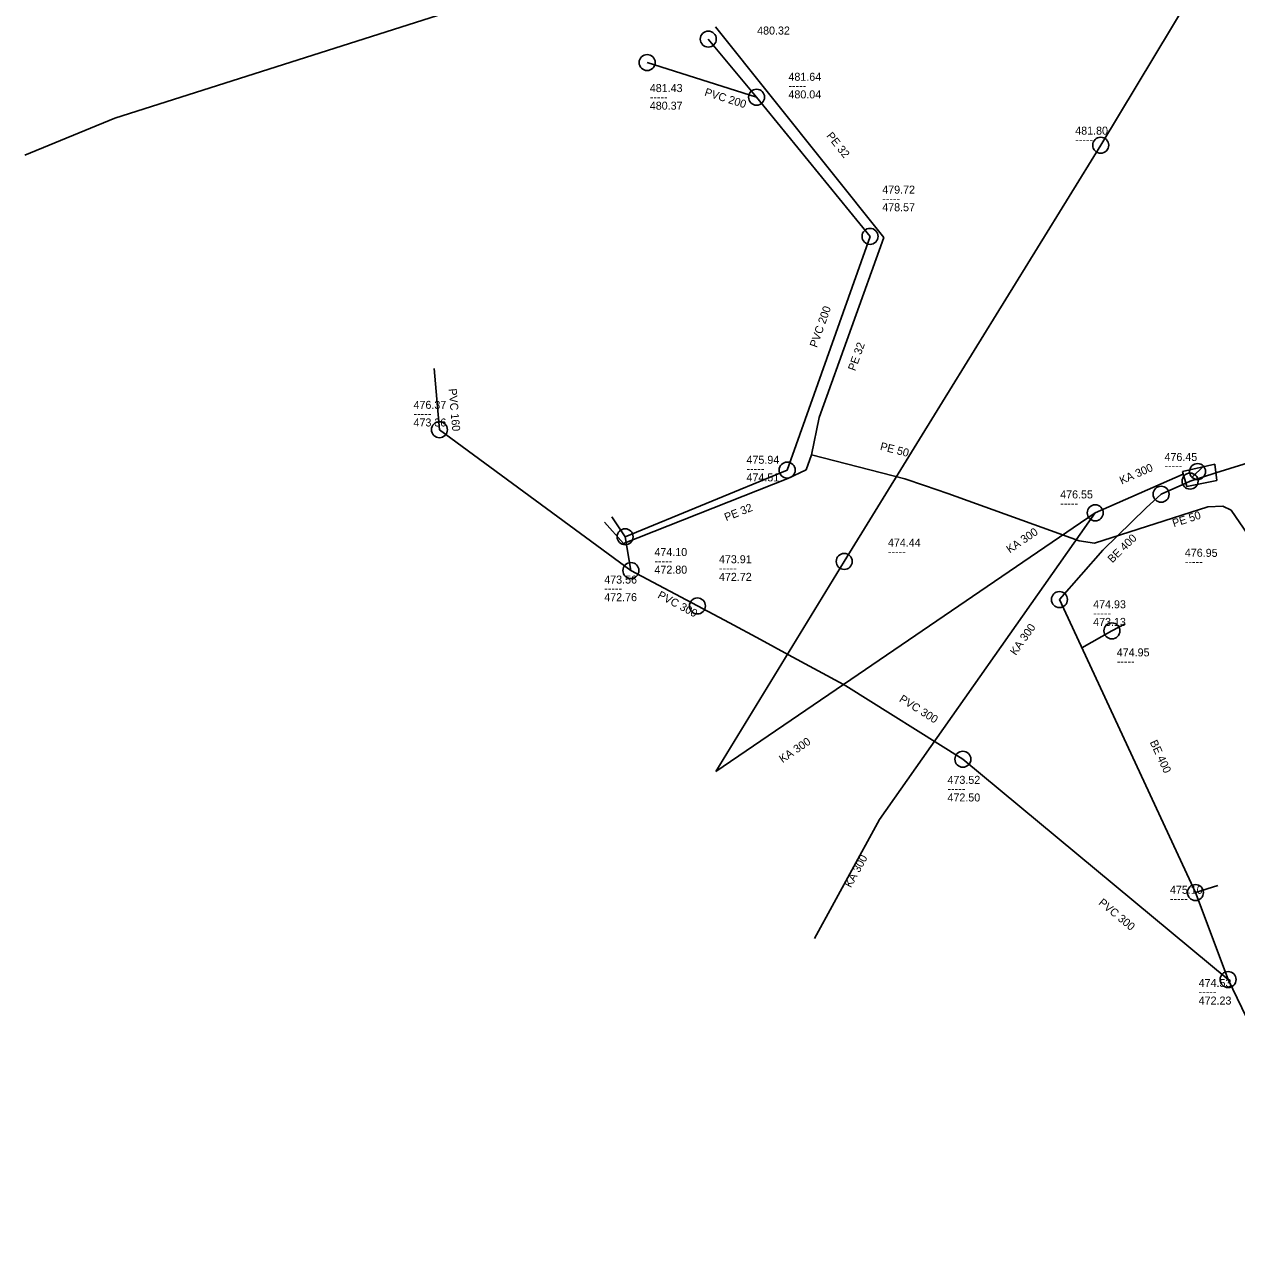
# Model space of a CAD drawing. Extents: x -685576 to -685145, y -1163436 to -1162895.
# Drawn here: x -685575.9 to -685424.5, y -1163249.3 to -1163094.7 of the extents above; entities that cross this region are included whole.
import ezdxf

# ---------------------------------------------------------------- set-up
doc = ezdxf.new("R2010")
doc.units = 0
doc.layers.add('Level 0', color=7, linetype='Continuous')

msp = doc.modelspace()

# ---------------------------------------------------------------- linework, layer by layer
at = {"layer": 'Level 0'}
for p, q in [((-685415.3, -1163066.26), (-685441.48, -1163109.74)), ((-685564.65, -1163106.35), (-685507.45, -1163088.13)), ((-685468.58, -1163121.27), (-685489.59, -1163094.93)), ((-685490.5, -1163096.48), (-685484.47, -1163103.74)), ((-685498.14, -1163099.41), (-685484.47, -1163103.74)), ((-685484.47, -1163103.74), (-685470.3, -1163121.13)), ((-685575.9, -1163110.98), (-685564.65, -1163106.35)), ((-685441.48, -1163109.74), (-685461.23, -1163141.8)), ((-685470.3, -1163121.13), (-685480.65, -1163150.34)), ((-685476.64, -1163143.78), (-685468.58, -1163121.27)), ((-685524.77, -1163137.65), (-685524.09, -1163145.29)), ((-685461.23, -1163141.8), (-685473.52, -1163161.75)), ((-685477.6, -1163148.45), (-685476.64, -1163143.78)), ((-685524.09, -1163145.29), (-685500.17, -1163162.89)), ((-685478.29, -1163150.31), (-685477.6, -1163148.45)), ((-685465.95, -1163151.42), (-685477.6, -1163148.45)), ((-685431.26, -1163150.5), (-685427.24, -1163149.59)), ((-685430.06, -1163151.24), (-685428.65, -1163149.84)), ((-685427.24, -1163149.59), (-685426.99, -1163151.64)), ((-685421.86, -1163149.04), (-685427.1, -1163150.7)), ((-685501.08, -1163159.52), (-685480.57, -1163151.37)), ((-685480.65, -1163150.34), (-685500.89, -1163158.67)), ((-685480.57, -1163151.37), (-685478.29, -1163150.31)), ((-685463.51, -1163152.26), (-685465.95, -1163151.42)), ((-685431.17, -1163150.84), (-685442.16, -1163155.68)), ((-685430.73, -1163152.41), (-685431.26, -1163150.5)), ((-685427.1, -1163150.7), (-685430.31, -1163151.72)), ((-685460.57, -1163153.27), (-685463.51, -1163152.26)), ((-685430.85, -1163151.97), (-685433.93, -1163153.36)), ((-685430.31, -1163151.72), (-685430.85, -1163151.97)), ((-685426.99, -1163151.64), (-685430.73, -1163152.41)), ((-685444.15, -1163159.2), (-685460.57, -1163153.27)), ((-685433.93, -1163153.36), (-685435.79, -1163155.04)), ((-685442.16, -1163155.68), (-685473.63, -1163177.15)), ((-685442.16, -1163155.68), (-685469.11, -1163194.02)), ((-685428.11, -1163154.92), (-685442.27, -1163159.47)), ((-685435.79, -1163155.04), (-685441.2, -1163160.33)), ((-685426.2, -1163154.83), (-685428.11, -1163154.92)), ((-685425.17, -1163155.33), (-685426.2, -1163154.83)), ((-685420.25, -1163162.58), (-685425.17, -1163155.33)), ((-685503.45, -1163156.85), (-685501.08, -1163159.52)), ((-685502.54, -1163156.16), (-685500.89, -1163158.67)), ((-685500.89, -1163158.67), (-685500.17, -1163162.89)), ((-685441.2, -1163160.33), (-685446.64, -1163166.52)), ((-685442.27, -1163159.47), (-685444.15, -1163159.2)), ((-685473.52, -1163161.75), (-685489.56, -1163188.02)), ((-685500.17, -1163162.89), (-685491.86, -1163167.32)), ((-685446.64, -1163166.52), (-685429.64, -1163203.13)), ((-685491.86, -1163167.32), (-685487.84, -1163169.43)), ((-685487.84, -1163169.43), (-685483.99, -1163171.52)), ((-685438.42, -1163169.57), (-685440.08, -1163170.43)), ((-685483.99, -1163171.52), (-685480.5, -1163173.42)), ((-685440.08, -1163170.43), (-685443.82, -1163172.57)), ((-685480.5, -1163173.42), (-685473.62, -1163177.13)), ((-685473.63, -1163177.15), (-685489.56, -1163188.02)), ((-685473.62, -1163177.13), (-685473.33, -1163177.29)), ((-685473.33, -1163177.29), (-685458.7, -1163186.47)), ((-685458.7, -1163186.47), (-685425.56, -1163214)), ((-685469.11, -1163194.02), (-685469.86, -1163195.39)), ((-685469.86, -1163195.39), (-685477.25, -1163208.86)), ((-685426.85, -1163202.27), (-685429.64, -1163203.13)), ((-685429.64, -1163203.13), (-685425.56, -1163214)), ((-685425.56, -1163214), (-685408.59, -1163249.33))]:
    msp.add_line(p, q, dxfattribs=at)
for centre in [(-685490.5, -1163096.48), (-685498.14, -1163099.41), (-685484.47, -1163103.74), (-685441.48, -1163109.74), (-685470.3, -1163121.13), (-685524.09, -1163145.29), (-685480.65, -1163150.34), (-685429.37, -1163150.52), (-685430.31, -1163151.72), (-685433.93, -1163153.36), (-685442.16, -1163155.68), (-685500.89, -1163158.67), (-685500.17, -1163162.89), (-685473.52, -1163161.75), (-685491.86, -1163167.32), (-685446.64, -1163166.52), (-685440.08, -1163170.43), (-685458.7, -1163186.47), (-685429.64, -1163203.13), (-685425.56, -1163214)]:
    msp.add_circle(centre, 1, dxfattribs=at)

# ---------------------------------------------------------------- texts
for s, p in [('480.32', (-685484.4, -1163095.91)), ('481.64', (-685480.49, -1163101.69)), ('481.43', (-685497.81, -1163103.1)), ('480.04', (-685480.49, -1163103.89)), ('-----', (-685480.49, -1163102.79)), ('480.37', (-685497.81, -1163105.3)), ('-----', (-685497.81, -1163104.2)), ('481.80', (-685444.66, -1163108.42)), ('-----', (-685444.66, -1163109.52)), ('479.72', (-685468.77, -1163115.79)), ('478.57', (-685468.77, -1163117.99)), ('-----', (-685468.77, -1163116.89)), ('476.37', (-685527.33, -1163142.69)), ('-----', (-685527.33, -1163143.79)), ('473.36', (-685527.33, -1163144.89)), ('476.45', (-685433.51, -1163149.2)), ('475.94', (-685485.73, -1163149.55)), ('-----', (-685433.51, -1163150.3)), ('474.51', (-685485.73, -1163151.75)), ('-----', (-685485.73, -1163150.65)), ('476.55', (-685446.54, -1163153.88)), ('-----', (-685446.54, -1163154.98)), ('474.44', (-685468.06, -1163159.9)), ('474.10', (-685497.23, -1163161.08)), ('-----', (-685468.06, -1163161)), ('-----', (-685497.23, -1163162.18)), ('473.91', (-685489.17, -1163161.98)), ('473.56', (-685503.5, -1163164.52)), ('472.80', (-685497.23, -1163163.28)), ('472.72', (-685489.17, -1163164.18)), ('-----', (-685489.17, -1163163.08)), ('-----', (-685503.5, -1163165.62)), ('472.76', (-685503.5, -1163166.72)), ('474.93', (-685442.42, -1163167.61)), ('-----', (-685442.42, -1163168.71)), ('473.13', (-685442.42, -1163169.81)), ('474.95', (-685439.47, -1163173.62)), ('-----', (-685439.47, -1163174.72)), ('473.52', (-685460.62, -1163189.55)), ('472.50', (-685460.62, -1163191.75)), ('-----', (-685460.62, -1163190.65)), ('475.10', (-685432.83, -1163203.29)), ('-----', (-685432.83, -1163204.39)), ('474.53', (-685429.24, -1163214.93)), ('472.23', (-685429.24, -1163217.13)), ('-----', (-685429.24, -1163216.03))]:
    msp.add_text(s, height=1, dxfattribs=at).set_placement(p)
for s, rotation, p in [('PVC 200', 342.424, (-685491.05, -1163103.52)), ('PE 32', 308.577, (-685475.8, -1163108.59)), ('PVC 200', 70.489, (-685476.94, -1163135.1)), ('PE 32', 70.299, (-685472.15, -1163138.02)), ('PVC 160', 275.086, (-685522.95, -1163140.19)), ('PE 50', 345.698, (-685469.11, -1163147.8)), ('KA 300', 23.776, (-685438.86, -1163152.15)), ('PE 32', 21.671, (-685488.26, -1163156.74)), ('PE 50', 17.814, (-685432.34, -1163157.49)), ('KA 300', 34.303, (-685452.84, -1163160.77)), ('BE 400', 44.357, (-685440.03, -1163162.01)), ('476.95', 359.456, (-685430.97, -1163161.15)), ('-----', 359.456, (-685430.97, -1163162.25)), ('PVC 300', 331.938, (-685496.92, -1163166.26)), ('KA 300', 54.896, (-685452.08, -1163173.57)), ('PVC 300', 327.893, (-685466.74, -1163179.19)), ('KA 300', 34.308, (-685481.23, -1163186.97)), ('BE 400', 294.908, (-685435.37, -1163184.34)), ('KA 300', 61.25, (-685472.68, -1163202.61)), ('PVC 300', 320.283, (-685441.83, -1163204.54))]:
    msp.add_text(s, height=1, rotation=rotation, dxfattribs=at).set_placement(p)

doc.saveas('drawing.dxf')
